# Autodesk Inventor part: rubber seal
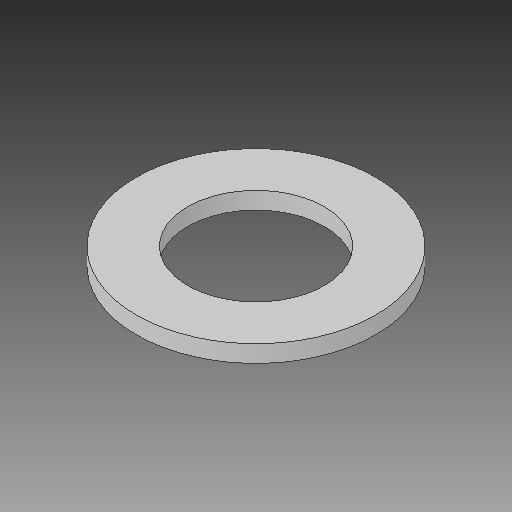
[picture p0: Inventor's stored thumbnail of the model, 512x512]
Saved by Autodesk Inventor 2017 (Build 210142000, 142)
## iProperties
Created: 2020-03
Part Number: rubber seal
Material: Generic
Document SubType Name: Modeling
Designer: user
Density: 1 g/cm^3
Appearance: Default
Author: user
Revision Number: ANY
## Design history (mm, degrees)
feature "Boss-Extrude1"
body "Solid1"
